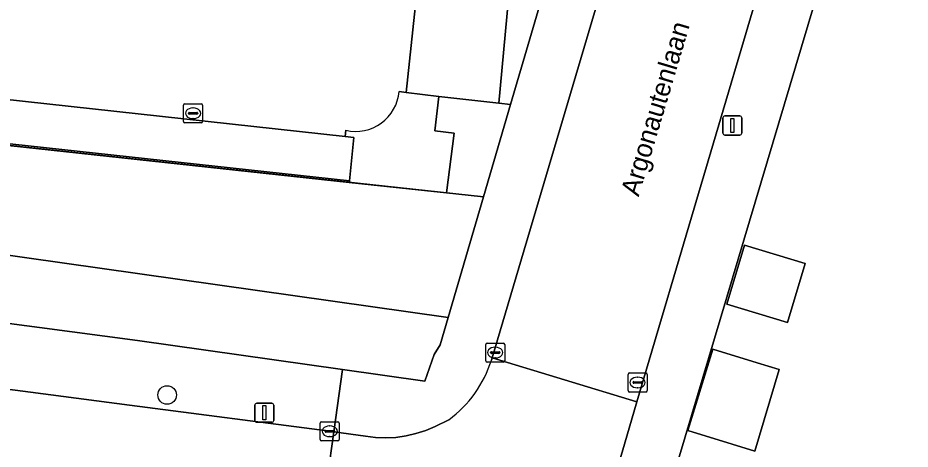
# Model space of a CAD drawing. Extents: x 162184 to 163154, y 385507 to 386516.
# Drawn here: x 162591.77 to 162638.71, y 386298.98 to 386321.64 of the extents above; entities that cross this region are included whole.
import ezdxf

# ---------------------------------------------------------------- set-up
doc = ezdxf.new("R2010")
doc.units = 0
for name, color, linetype in [('IMGEO_Boom', 7, 'Continuous'), ('IMGEO_Erf', 7, 'Continuous'), ('IMGEO_Groenvoorziening', 7, 'Continuous'), ('IMGEO_Haag', 7, 'Continuous'), ('IMGEO_Hek', 7, 'Continuous'), ('IMGEO_Kolk', 7, 'Continuous'), ('IMGEO_Lichtmast', 7, 'Continuous'), ('IMGEO_Openbare_ruimte_label', 7, 'Continuous'), ('IMGEO_Pand', 7, 'Continuous'), ('IMGEO_Parkeervlak_open', 7, 'Continuous'), ('IMGEO_Rijbaan_lokaal_open', 7, 'Continuous'), ('IMGEO_Voetpad_open', 7, 'Continuous')]:
    doc.layers.add(name, color=color, linetype=linetype)

msp = doc.modelspace()

# ---------------------------------------------------------------- linework, layer by layer
at = {"layer": 'IMGEO_Boom'}
msp.add_circle((162599.62, 386301.823), 0.489, dxfattribs=at)
at = {"layer": 'IMGEO_Erf'}
msp.add_lwpolyline([(162655.987, 386313.896), (162638.065, 386325.703), (162637.869, 386325.818), (162637.664, 386325.916), (162637.451, 386325.995), (162637.232, 386326.054), (162637.008, 386326.093), (162636.781, 386326.113), (162636.554, 386326.112), (162636.328, 386326.091), (162636.105, 386326.049), (162635.886, 386325.988), (162635.673, 386325.908), (162635.469, 386325.809), (162635.274, 386325.692), (162635.091, 386325.558), (162634.92, 386325.408), (162634.763, 386325.244), (162634.621, 386325.066), (162634.496, 386324.876), (162634.389, 386324.676), (162634.3, 386324.467), (162634.243, 386324.299), (162615.574, 386261.809)], dxfattribs=at)
for points in [[(162629.058, 386306.596), (162629.988, 386309.697), (162633.187, 386308.738), (162632.257, 386305.636)], [(162630.531, 386298.877), (162629.349, 386299.238), (162627.014, 386299.951), (162628.32, 386304.23), (162630.655, 386303.517), (162631.816, 386303.163)]]:
    msp.add_lwpolyline(points, close=True, dxfattribs=at)
at = {"layer": 'IMGEO_Groenvoorziening'}
for points in [[(162618.014, 386327.383), (162617.066, 386317.149), (162617.681, 386317.081), (162619.799, 386324.298)], [(162509.176, 386316.263), (162550.981, 386310.895), (162592.901, 386305.371), (162598.062, 386304.691), (162608.854, 386303.164), (162613.176, 386302.552), (162613.669, 386303.958), (162613.979, 386304.464), (162614.397, 386305.888), (162557.685, 386313.92), (162505.963, 386320.438)]]:
    msp.add_lwpolyline(points, dxfattribs=at)
for points in [[(162519.646, 386322.715), (162512.634, 386323.476), (162510.71, 386323.704), (162510.401, 386323.741), (162510.217, 386322.39), (162506.322, 386322.895), (162506.272, 386322.552), (162505.963, 386320.438), (162557.685, 386313.92), (162614.397, 386305.888), (162616.257, 386312.229), (162614.31, 386312.44), (162609.205, 386312.994)], [(162617.681, 386317.081), (162617.066, 386317.149), (162613.913, 386317.5), (162613.699, 386315.712), (162614.723, 386315.589), (162614.31, 386312.44), (162616.257, 386312.229)]]:
    msp.add_lwpolyline(points, close=True, dxfattribs=at)
at = {"layer": 'IMGEO_Haag'}
msp.add_lwpolyline([(162617.681, 386317.081), (162617.066, 386317.149), (162613.913, 386317.5), (162613.699, 386315.712), (162614.723, 386315.589), (162614.31, 386312.44), (162616.257, 386312.229)], close=True, dxfattribs=at)
at = {"layer": 'IMGEO_Hek'}
msp.add_lwpolyline([(162616.257, 386312.229), (162512.634, 386323.476)], dxfattribs=at)
at = {"layer": 'IMGEO_Kolk'}
for p, q in [((162600.485, 386316.199), (162600.485, 386317.051)), ((162600.56, 386317.125), (162601.412, 386317.125)), ((162600.973, 386316.905), (162600.998, 386316.905)), ((162601.486, 386317.051), (162601.486, 386316.199)), ((162600.744, 386316.619), (162600.744, 386316.631)), ((162601.182, 386316.582), (162600.784, 386316.582)), ((162600.787, 386316.668), (162601.185, 386316.668)), ((162600.996, 386316.345), (162600.971, 386316.345)), ((162601.228, 386316.631), (162601.228, 386316.619)), ((162601.412, 386316.125), (162600.56, 386316.125)), ((162616.379, 386303.625), (162616.379, 386304.477)), ((162616.454, 386304.551), (162617.306, 386304.551)), ((162617.38, 386304.477), (162617.38, 386303.625)), ((162616.638, 386304.045), (162616.638, 386304.057)), ((162617.076, 386304.008), (162616.678, 386304.008)), ((162616.681, 386304.094), (162617.079, 386304.094)), ((162616.867, 386304.331), (162616.892, 386304.331)), ((162617.122, 386304.057), (162617.122, 386304.045)), ((162617.306, 386303.551), (162616.454, 386303.551)), ((162616.89, 386303.771), (162616.865, 386303.771)), ((162623.868, 386302.054), (162623.868, 386302.906)), ((162623.943, 386302.98), (162624.795, 386302.98)), ((162624.356, 386302.76), (162624.381, 386302.76)), ((162624.869, 386302.906), (162624.869, 386302.054)), ((162624.127, 386302.474), (162624.127, 386302.486)), ((162624.565, 386302.437), (162624.167, 386302.437)), ((162624.17, 386302.523), (162624.568, 386302.523)), ((162624.379, 386302.2), (162624.354, 386302.2)), ((162624.611, 386302.486), (162624.611, 386302.474)), ((162624.795, 386301.98), (162623.943, 386301.98)), ((162607.674, 386299.489), (162607.674, 386300.341)), ((162607.749, 386300.415), (162608.601, 386300.415)), ((162608.675, 386300.341), (162608.675, 386299.489)), ((162607.933, 386299.909), (162607.933, 386299.921)), ((162608.371, 386299.872), (162607.973, 386299.872)), ((162607.976, 386299.958), (162608.374, 386299.958)), ((162608.162, 386300.195), (162608.187, 386300.195)), ((162608.417, 386299.921), (162608.417, 386299.909)), ((162608.601, 386299.415), (162607.749, 386299.415)), ((162608.185, 386299.635), (162608.16, 386299.635))]:
    msp.add_line(p, q, dxfattribs=at)
for points in [[(162600.485, 386316.199), (162600.485, 386317.051)], [(162600.56, 386317.125), (162601.412, 386317.125)], [(162601.486, 386317.051), (162601.486, 386316.199)], [(162601.412, 386316.125), (162600.56, 386316.125)], [(162616.379, 386303.625), (162616.379, 386304.477)], [(162616.454, 386304.551), (162617.306, 386304.551)], [(162617.38, 386304.477), (162617.38, 386303.625)], [(162617.306, 386303.551), (162616.454, 386303.551)], [(162623.868, 386302.054), (162623.868, 386302.906)], [(162623.943, 386302.98), (162624.795, 386302.98)], [(162624.869, 386302.906), (162624.869, 386302.054)], [(162624.795, 386301.98), (162623.943, 386301.98)], [(162607.674, 386299.489), (162607.674, 386300.341)], [(162607.749, 386300.415), (162608.601, 386300.415)], [(162608.675, 386300.341), (162608.675, 386299.489)], [(162608.601, 386299.415), (162607.749, 386299.415)]]:
    msp.add_lwpolyline(points, dxfattribs=at)
for centre, radius, start, end in [((162600.562, 386317.049), 0.0765, 91.552, 178.448), ((162600.562, 386317.049), 0.0765, 91.552, 178.448), ((162601.41, 386317.049), 0.0765, 1.552, 88.448), ((162601.41, 386317.049), 0.0765, 1.552, 88.448), ((162600.784, 386316.628), 0.0403, 85.8775, 175.7526), ((162600.781, 386316.618), 0.0366, 178.938, 274.7102), ((162601.185, 386316.625), 0.043, 264.8664, 352.4533), ((162601.189, 386316.63), 0.0386, 1.7309, 96.639), ((162600.562, 386316.201), 0.0765, 181.552, 268.448), ((162600.562, 386316.201), 0.0765, 181.552, 268.448), ((162601.41, 386316.201), 0.0765, 271.552, 358.448), ((162601.41, 386316.201), 0.0765, 271.552, 358.448), ((162616.456, 386304.475), 0.0765, 91.552, 178.448), ((162616.456, 386304.475), 0.0765, 91.552, 178.448), ((162617.304, 386304.475), 0.0765, 1.552, 88.448), ((162617.304, 386304.475), 0.0765, 1.552, 88.448), ((162616.678, 386304.054), 0.0403, 85.8775, 175.7526), ((162616.675, 386304.044), 0.0366, 178.938, 274.7102), ((162617.079, 386304.051), 0.043, 264.8664, 352.4533), ((162617.083, 386304.056), 0.0386, 1.7309, 96.639), ((162616.456, 386303.627), 0.0765, 181.552, 268.448), ((162616.456, 386303.627), 0.0765, 181.552, 268.448), ((162617.304, 386303.627), 0.0765, 271.552, 358.448), ((162617.304, 386303.627), 0.0765, 271.552, 358.448), ((162623.945, 386302.904), 0.0765, 91.552, 178.448), ((162623.945, 386302.904), 0.0765, 91.552, 178.448), ((162624.793, 386302.904), 0.0765, 1.552, 88.448), ((162624.793, 386302.904), 0.0765, 1.552, 88.448), ((162624.167, 386302.483), 0.0403, 85.8775, 175.7526), ((162624.164, 386302.473), 0.0366, 178.938, 274.7102), ((162624.568, 386302.48), 0.043, 264.8664, 352.4533), ((162624.572, 386302.485), 0.0386, 1.7309, 96.639), ((162623.945, 386302.056), 0.0765, 181.552, 268.448), ((162623.945, 386302.056), 0.0765, 181.552, 268.448), ((162624.793, 386302.056), 0.0765, 271.552, 358.448), ((162624.793, 386302.056), 0.0765, 271.552, 358.448), ((162607.751, 386300.339), 0.0765, 91.552, 178.448), ((162607.751, 386300.339), 0.0765, 91.552, 178.448), ((162608.599, 386300.339), 0.0765, 1.552, 88.448), ((162608.599, 386300.339), 0.0765, 1.552, 88.448), ((162607.973, 386299.918), 0.0403, 85.8775, 175.7526), ((162607.97, 386299.908), 0.0366, 178.938, 274.7102), ((162608.374, 386299.915), 0.043, 264.8664, 352.4533), ((162608.378, 386299.92), 0.0386, 1.7309, 96.639), ((162607.751, 386299.491), 0.0765, 181.552, 268.448), ((162607.751, 386299.491), 0.0765, 181.552, 268.448), ((162608.599, 386299.491), 0.0765, 271.552, 358.448), ((162608.599, 386299.491), 0.0765, 271.552, 358.448)]:
    msp.add_arc(centre, radius, start, end, dxfattribs=at)
for centre, major_axis, ratio, start_param, end_param in [((162600.972, 386316.625), (-0.387, 0.002), 0.722429, 4.712389, 7.853982), ((162600.997, 386316.625), (-0.39, 0.002), 0.717154, 1.570796, 4.712389), ((162616.866, 386304.051), (-0.387, 0.002), 0.722429, 4.712389, 7.853982), ((162616.891, 386304.051), (-0.39, 0.002), 0.717154, 1.570796, 4.712389), ((162624.355, 386302.48), (-0.387, 0.002), 0.722429, 4.712389, 7.853982), ((162624.38, 386302.48), (-0.39, 0.002), 0.717154, 1.570796, 4.712389), ((162608.161, 386299.915), (-0.387, 0.002), 0.722429, 4.712389, 7.853982), ((162608.186, 386299.915), (-0.39, 0.002), 0.717154, 1.570796, 4.712389)]:
    msp.add_ellipse(centre, major_axis=major_axis, ratio=ratio, start_param=start_param, end_param=end_param, dxfattribs=at)
at = {"layer": 'IMGEO_Lichtmast'}
for p, q in [((162628.855, 386315.584), (162628.855, 386316.384)), ((162628.855, 386316.384), (162628.855, 386315.584)), ((162628.955, 386316.484), (162629.745, 386316.484)), ((162629.745, 386316.484), (162628.955, 386316.484)), ((162629.845, 386316.384), (162629.845, 386315.584)), ((162629.845, 386315.584), (162629.845, 386316.384)), ((162629.745, 386315.484), (162628.955, 386315.484)), ((162628.955, 386315.484), (162629.745, 386315.484)), ((162604.235, 386300.488), (162604.235, 386301.288)), ((162604.235, 386301.288), (162604.235, 386300.488)), ((162604.335, 386301.388), (162605.125, 386301.388)), ((162605.125, 386301.388), (162604.335, 386301.388)), ((162605.225, 386301.288), (162605.225, 386300.488)), ((162605.225, 386300.488), (162605.225, 386301.288)), ((162605.125, 386300.388), (162604.335, 386300.388)), ((162604.335, 386300.388), (162605.125, 386300.388))]:
    msp.add_line(p, q, dxfattribs=at)
for points in [[(162629.275, 386316.359), (162629.425, 386316.359), (162629.425, 386315.609), (162629.275, 386315.609), (162629.275, 386316.359)], [(162604.655, 386301.263), (162604.805, 386301.263), (162604.805, 386300.513), (162604.655, 386300.513), (162604.655, 386301.263)]]:
    msp.add_lwpolyline(points, dxfattribs=at)
for centre, start, end in [((162628.955, 386316.384), 90, 180), ((162628.955, 386316.384), 90, 180), ((162629.745, 386316.384), 0, 90), ((162629.745, 386316.384), 360, 90), ((162628.955, 386315.584), 180, 270), ((162628.955, 386315.584), 180, 270), ((162629.745, 386315.584), 270, 0), ((162629.745, 386315.584), 270, 0), ((162604.335, 386301.288), 90, 180), ((162604.335, 386301.288), 90, 180), ((162605.125, 386301.288), 0, 90), ((162605.125, 386301.288), 360, 90), ((162604.335, 386300.488), 180, 270), ((162604.335, 386300.488), 180, 270), ((162605.125, 386300.488), 270, 0), ((162605.125, 386300.488), 270, 0)]:
    msp.add_arc(centre, 0.1, start, end, dxfattribs=at)
at = {"layer": 'IMGEO_Pand'}
for points in [[(162553.4, 386321.48), (162553.169, 386319.178), (162609.214, 386313.083), (162609.447, 386315.355), (162608.983, 386315.406)], [(162629.058, 386306.596), (162632.257, 386305.636), (162633.187, 386308.738), (162629.988, 386309.697)], [(162630.655, 386303.517), (162628.32, 386304.23), (162627.014, 386299.951), (162629.349, 386299.238), (162630.531, 386298.877), (162631.816, 386303.163)]]:
    msp.add_lwpolyline(points, close=True, dxfattribs=at)
at = {"layer": 'IMGEO_Parkeervlak_open'}
msp.add_lwpolyline([(162615.48, 386348.527), (162612.202, 386317.718), (162613.913, 386317.5), (162617.066, 386317.149), (162618.014, 386327.383), (162617.087, 386327.424), (162617.452, 386330.578), (162618.22, 386330.538), (162620.468, 386348.038)], close=True, dxfattribs=at)
at = {"layer": 'IMGEO_Rijbaan_lokaal_open'}
for points in [[(162611.824, 386317.767), (162612.202, 386317.718), (162615.48, 386348.527), (162615.55, 386348.908), (162615.651, 386349.281), (162615.784, 386349.644), (162615.948, 386349.995), (162616.141, 386350.33), (162616.361, 386350.648), (162616.608, 386350.946), (162616.879, 386351.222), (162617.173, 386351.474), (162617.487, 386351.701), (162617.819, 386351.899), (162618.167, 386352.069), (162618.528, 386352.208), (162618.899, 386352.316), (162619.279, 386352.393), (162619.663, 386352.436), (162620.05, 386352.447), (162620.436, 386352.425), (162625.675, 386351.949), (162626.487, 386359.049)], [(162637.062, 386342.879), (162637.167, 386343.619), (162634.25, 386343.989), (162634.38, 386344.979), (162633.803, 386345.113), (162629.39, 386345.625), (162629.196, 386344.588), (162623.836, 386327.782), (162616.714, 386303.774), (162624.336, 386301.463), (162631.102, 386324.317)], [(162519.646, 386322.715), (162609.205, 386312.994), (162609.214, 386313.083), (162553.169, 386319.178), (162553.4, 386321.48), (162608.983, 386315.406), (162609.021, 386315.734)], [(162543.961, 386301.114), (162549.973, 386300.35), (162558.903, 386299.215), (162607.392, 386292.738), (162608.395, 386299.882), (162608.171, 386299.914), (162597.633, 386301.29), (162592.437, 386301.969), (162586.759, 386302.71), (162557.5, 386306.343), (162551.376, 386307.147), (162505.895, 386313.114)], [(162623.677, 386299.236), (162624.336, 386301.463), (162616.714, 386303.774), (162616.68, 386303.658)], [(162614.433, 386300.518), (162613.713, 386300.175), (162613.221, 386299.962), (162612.712, 386299.794), (162612.189, 386299.673), (162611.658, 386299.598), (162611.123, 386299.571), (162610.587, 386299.592), (162610.055, 386299.661), (162608.395, 386299.882), (162607.392, 386292.738)], [(162611.367, 386286.414), (162619.204, 386284.067), (162623.677, 386299.236)]]:
    msp.add_lwpolyline(points, dxfattribs=at)
for centre, radius, start, end in [((162609.542, 386317.964), 2.29, 256.8437, 355.0626), ((162610.736, 386305.537), 6.234, 306.3711, 342.4535)]:
    msp.add_arc(centre, radius, start, end, dxfattribs=at)
at = {"layer": 'IMGEO_Voetpad_open'}
for points in [[(162622.361, 386333.03), (162620.272, 386325.912), (162619.799, 386324.298), (162617.681, 386317.081), (162616.257, 386312.229), (162614.397, 386305.888), (162613.979, 386304.464), (162613.669, 386303.958), (162613.176, 386302.552), (162608.854, 386303.164), (162608.395, 386299.882), (162610.055, 386299.661), (162610.587, 386299.592), (162611.123, 386299.571), (162611.658, 386299.598), (162612.189, 386299.673), (162612.712, 386299.794), (162613.221, 386299.962), (162613.713, 386300.175), (162614.433, 386300.518)], [(162616.68, 386303.658), (162616.714, 386303.774), (162623.836, 386327.782)], [(162631.102, 386324.317), (162624.336, 386301.463), (162623.677, 386299.236), (162619.204, 386284.067), (162613.26, 386264.222), (162609.006, 386250), (162604.039, 386233.483), (162606.797, 386232.654), (162609.673, 386231.789)], [(162607.649, 386235.575), (162611.995, 386250), (162612.998, 386253.328), (162613.032, 386253.495), (162615.469, 386261.509), (162615.574, 386261.809), (162634.243, 386324.299)], [(162613.913, 386317.5), (162612.202, 386317.718), (162611.824, 386317.767)], [(162609.021, 386315.734), (162608.983, 386315.406), (162609.447, 386315.355), (162609.214, 386313.083), (162609.205, 386312.994), (162614.31, 386312.44), (162614.723, 386315.589), (162613.699, 386315.712), (162613.913, 386317.5)]]:
    msp.add_lwpolyline(points, dxfattribs=at)
msp.add_lwpolyline([(162509.176, 386316.263), (162505.38, 386316.75), (162500, 386317.441), (162495.408, 386318.031), (162491.222, 386318.605), (162437.933, 386325.465), (162431.169, 386326.378), (162430.717, 386322.917), (162499.627, 386313.936), (162500, 386313.887), (162505.895, 386313.114), (162551.376, 386307.147), (162557.5, 386306.343), (162586.759, 386302.71), (162592.437, 386301.969), (162597.633, 386301.29), (162608.171, 386299.914), (162608.395, 386299.882), (162608.854, 386303.164), (162598.062, 386304.691), (162592.901, 386305.371), (162550.981, 386310.895)], close=True, dxfattribs=at)
for centre, radius, start, end in [((162609.542, 386317.964), 2.29, 256.8437, 355.0626), ((162610.736, 386305.537), 6.234, 306.3711, 342.4535)]:
    msp.add_arc(centre, radius, start, end, dxfattribs=at)

# ---------------------------------------------------------------- texts
at = {"layer": 'IMGEO_Openbare_ruimte_label'}
msp.add_text('Argonautenlaan', height=1, rotation=73.3776, dxfattribs=at).set_placement((162624.423, 386312.212))

doc.saveas('drawing.dxf')
